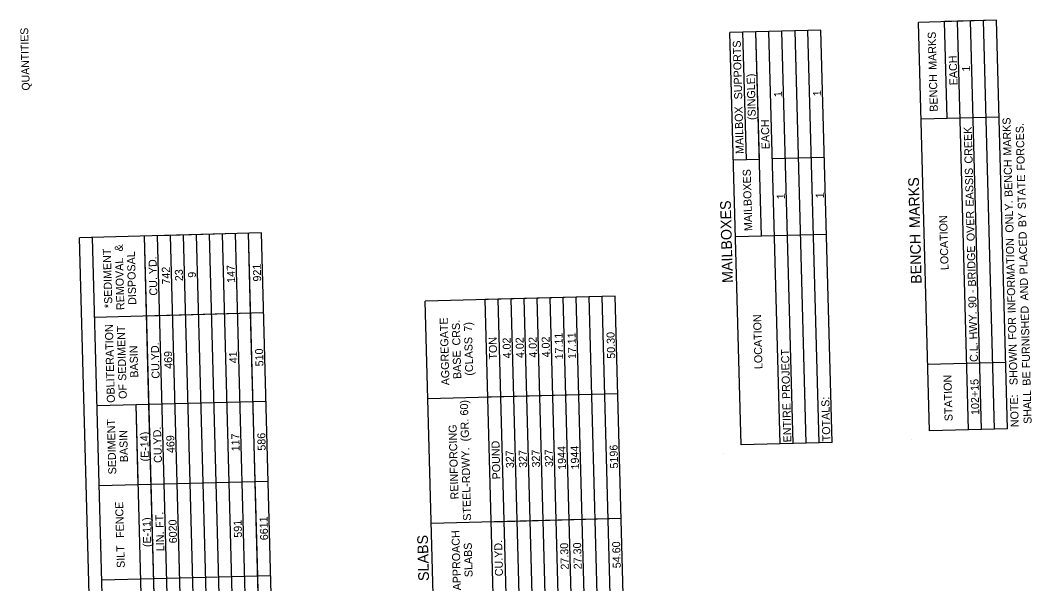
# Model space of a CAD drawing. Extents: x 1930091 to 1931962, y 596452 to 607874.
# Drawn here: x 1930287 to 1931046, y 600225 to 600647 of the extents above; entities that cross this region are included whole.
import ezdxf

# ---------------------------------------------------------------- set-up
doc = ezdxf.new("R2010")
doc.units = 0
for name, color, linetype in [('Default', 7, 'Continuous'), ('R_Border', 7, 'Continuous'), ('S_AREA_CALC', 7, 'Continuous')]:
    doc.layers.add(name, color=color, linetype=linetype)

msp = doc.modelspace()

# ---------------------------------------------------------------- linework, layer by layer
at = {"layer": 'Default'}
for p, q in [((1931019.12, 600647.31), (1930960.64, 600645.74)), ((1930968.85, 600339.7), (1930960.64, 600645.74)), ((1931019.12, 600647.31), (1930980.13, 600646.26)), ((1930982.08, 600573.65), (1930980.13, 600646.26)), ((1930998.09, 600340.48), (1930989.88, 600646.52)), ((1931007.84, 600340.74), (1930999.62, 600646.78)), ((1931017.58, 600341.01), (1931009.37, 600647.05)), ((1931027.33, 600341.27), (1931019.12, 600647.31)), ((1930887.59, 600639.9), (1930819.36, 600638.07)), ((1930829.11, 600638.33), (1930819.36, 600638.07)), ((1930827.66, 600329.1), (1930819.36, 600638.07)), ((1930831.68, 600542.81), (1930829.11, 600638.33)), ((1930887.59, 600639.9), (1930838.86, 600638.59)), ((1930842.97, 600485.57), (1930838.86, 600638.59)), ((1930841.42, 600543.08), (1930838.86, 600638.59)), ((1930856.9, 600329.89), (1930848.6, 600638.85)), ((1930866.64, 600330.15), (1930858.35, 600639.11)), ((1930876.39, 600330.41), (1930868.1, 600639.38)), ((1930886.14, 600330.67), (1930877.84, 600639.64)), ((1930895.88, 600330.94), (1930887.59, 600639.9)), ((1931021.06, 600574.7), (1930962.59, 600573.13)), ((1931021.06, 600574.7), (1930991.83, 600573.91)), ((1930841.42, 600543.08), (1930821.93, 600542.55)), ((1930890.15, 600544.38), (1930851.17, 600543.34)), ((1930890.15, 600544.38), (1930851.17, 600543.34)), ((1930468.12, 600487.92), (1930331.67, 600484.26)), ((1930458.38, 600487.66), (1930390.15, 600485.83)), ((1930443.87, 599211.51), (1930409.65, 600486.35)), ((1930453.61, 599211.78), (1930419.39, 600486.62)), ((1930463.36, 599212.04), (1930429.14, 600486.88)), ((1930473.11, 599212.3), (1930438.88, 600487.14)), ((1930482.85, 599212.56), (1930448.63, 600487.4)), ((1930492.6, 599212.82), (1930458.38, 600487.66)), ((1930459.99, 600427.72), (1930458.38, 600487.66)), ((1930502.35, 599213.08), (1930468.12, 600487.92)), ((1930891.7, 600486.88), (1930823.47, 600485.05)), ((1930891.7, 600486.88), (1930852.71, 600485.83)), ((1930365.9, 599209.42), (1930331.67, 600484.26)), ((1930366.93, 599534.24), (1930341.42, 600484.52)), ((1930405.92, 599535.29), (1930380.41, 600485.57)), ((1930383.79, 600359.35), (1930380.41, 600485.57)), ((1930424.37, 599210.99), (1930390.15, 600485.83)), ((1930434.12, 599211.25), (1930399.9, 600486.09)), ((1930733.24, 600440.58), (1930590.94, 600436.76)), ((1930605.18, 599906.55), (1930590.94, 600436.76)), ((1930733.24, 600440.58), (1930635.78, 600437.97)), ((1930643.13, 600164.09), (1930635.78, 600437.97)), ((1930659.76, 599908.02), (1930645.52, 600438.23)), ((1930669.5, 599908.28), (1930655.27, 600438.49)), ((1930679.25, 599908.54), (1930665.02, 600438.75)), ((1930689, 599908.8), (1930674.76, 600439.01)), ((1930698.74, 599909.07), (1930684.51, 600439.28)), ((1930708.49, 599909.33), (1930694.26, 600439.54)), ((1930718.24, 599909.59), (1930704, 600439.8)), ((1930727.98, 599909.85), (1930713.75, 600440.06)), ((1930737.73, 599910.11), (1930723.5, 600440.32)), ((1930747.47, 599910.37), (1930733.24, 600440.58)), ((1930469.73, 600427.98), (1930343.03, 600424.58)), ((1930469.73, 600427.98), (1930382.01, 600425.63)), ((1930465.27, 600230.84), (1930459.99, 600427.72)), ((1931026, 600390.97), (1930967.52, 600389.4)), ((1930735.2, 600367.49), (1930592.91, 600363.67)), ((1930735.2, 600367.49), (1930637.74, 600364.87)), ((1930471.51, 600361.71), (1930344.81, 600358.31)), ((1930380.82, 600106.66), (1930374.05, 600359.09)), ((1930375.66, 600299.15), (1930374.05, 600359.09)), ((1930471.51, 600361.71), (1930383.79, 600359.35)), ((1930392.56, 600032.85), (1930383.79, 600359.35)), ((1931027.33, 600341.27), (1930968.85, 600339.7)), ((1931027.33, 600341.27), (1930968.85, 600339.7)), ((1930895.88, 600330.94), (1930827.66, 600329.1)), ((1930895.88, 600330.94), (1930827.66, 600329.1)), ((1930473.12, 600301.77), (1930346.42, 600298.37)), ((1930473.12, 600301.77), (1930385.4, 600299.41)), ((1930737.72, 600273.92), (1930595.42, 600270.1)), ((1930737.72, 600273.92), (1930640.25, 600271.3)), ((1930475.02, 600231.1), (1930348.31, 600227.7)), ((1930465.27, 600230.84), (1930387.3, 600228.75)), ((1930474.57, 599884.36), (1930465.27, 600230.84))]:
    msp.add_line(p, q, dxfattribs=at)
at = {"layer": 'R_Border'}
for p, q in [((1930955.36, 600333.48), (1930955.36, 600333.48)), ((1930814.17, 600322.89), (1930814.17, 600322.89))]:
    msp.add_line(p, q, dxfattribs=at)

# ---------------------------------------------------------------- texts
at = {"layer": 'Default'}
for s, height, p in [(' MARKS', 6, (1930974.4, 600608.03)), (' SUPPORTS', 6, (1930828.64, 600585.83)), ('EACH', 6, (1930989.96, 600598.63)), ('1', 6, (1930999.44, 600608.89)), ('(SINGLE)', 6, (1930838.75, 600572.61)), ('BENCH', 6, (1930975.19, 600578.87)), ('1', 6, (1930858.47, 600589.77)), ('1', 6, (1930887.72, 600590.46)), ('MAILBOX', 6, (1930829.68, 600547.19)), ('EACH', 6, (1930849.09, 600550.74)), (' MARKS', 6, (1931030.45, 600543.71)), (' CREEK', 6, (1931001.35, 600537.75)), (' FORCES.', 6, (1931040.5, 600532.47)), (' BENCH', 6, (1931031.28, 600512.72)), ('MAILBOXES', 6, (1930836.11, 600489.44)), (' EASSIS', 6, (1931002.21, 600505.58)), (' MARKS', 8, (1930962.02, 600488.76)), (' STATE', 6, (1931041.28, 600503.58)), ('1', 6, (1930860.53, 600513.26)), ('1', 6, (1930889.77, 600513.95)), ('MAILBOXES', 8, (1930821.57, 600450.57)), (' ONLY.', 6, (1931032, 600485.98)), (' OVER', 6, (1931002.91, 600479.61)), (' BY', 6, (1931041.64, 600490.14)), ('LOCATION', 6, (1930983.25, 600460.19)), ('BENCH', 8, (1930963.07, 600449.89)), (' PLACED', 6, (1931042.59, 600454.72)), (' &', 6, (1930364.27, 600471.86)), (' INFORMATION', 6, (1931033.62, 600425.67)), ('*SEDIMENT', 6, (1930356.34, 600431.72)), ('DISPOSAL', 6, (1930374.28, 600434.1)), (' BRIDGE', 6, (1931003.82, 600445.6)), ('REMOVAL', 6, (1930365.39, 600430.21)), (' YD.', 6, (1930389.78, 600454.9)), ('921', 6, (1930467.9, 600451.61)), ('742', 6, (1930399.69, 600449.32)), ('23', 6, (1930409.37, 600451.88)), ('9', 6, (1930419.05, 600454.47)), ('147', 6, (1930448.42, 600450.6)), ('CU.', 6, (1930390.15, 600441.04)), (' AND', 6, (1931043.12, 600435.15)), (' -', 6, (1931003.95, 600440.74)), (' 90', 6, (1931004.25, 600429.5)), ('LOCATION', 6, (1930843.76, 600386)), (' HWY.', 6, (1931004.88, 600406.03)), (' FURNISHED', 6, (1931044.48, 600384.38)), ('OBLITERATION', 6, (1930358.25, 600360.72)), (' SEDIMENT', 6, (1930366.87, 600374.94)), ('AGGREGATE', 6, (1930609.06, 600373.85)), (' CRS.', 6, (1930617.33, 600401.45)), (' 7)', 6, (1930626.05, 600411.86)), (' FOR', 6, (1931034.15, 600405.77)), ('17.11', 6, (1930694.3, 600393.25)), ('17.11', 6, (1930704.04, 600393.51)), ('50.30', 6, (1930733.3, 600393.73)), ('BASIN', 6, (1930375.75, 600379.59)), ('CU.YD.', 6, (1930391.82, 600378.81)), ('(CLASS', 6, (1930626.88, 600381.08)), ('TON', 6, (1930644.86, 600393.12)), ('4.02', 6, (1930655.26, 600393.98)), ('4.02', 6, (1930665.01, 600394.24)), ('4.02', 6, (1930674.76, 600394.5)), ('4.02', 6, (1930684.5, 600394.76)), ('C.L.', 6, (1931005.28, 600391.39)), ('   SHOWN', 6, (1931035.18, 600367.35)), ('469', 6, (1930401.38, 600386.18)), ('41', 6, (1930450.03, 600390.4)), ('510', 6, (1930469.61, 600388.03)), ('BASE', 6, (1930617.94, 600378.57)), (' PROJECT', 6, (1930864.61, 600361.38)), ('STATION', 6, (1930986.29, 600346.97)), (' BE', 6, (1931044.83, 600371.31)), ('OF', 6, (1930367.17, 600363.69)), ('102+15', 6, (1931006.34, 600351.64)), ('NOTE:', 6, (1931035.85, 600342.47)), (' SHALL', 6, (1931045.6, 600342.73)), (' 60)', 6, (1930623.24, 600348.98)), ('ENTIRE', 6, (1930865.42, 600331.09)), ('TOTALS:', 6, (1930894.66, 600331.88)), ('SEDIMENT', 6, (1930359.31, 600307.12)), ('REINFORCING', 6, (1930615.86, 600288.36)), (' (GR.', 6, (1930623.76, 600329.55)), ('BASIN', 6, (1930368.07, 600316.23)), ('(E-14)', 6, (1930383.74, 600316.77)), ('CU.YD.', 6, (1930393.52, 600315.7)), ('469', 6, (1930403.07, 600323.07)), ('117', 6, (1930451.81, 600324.38)), ('586', 6, (1930471.3, 600324.87)), ('POUND', 6, (1930647.27, 600303.37)), ('1944', 6, (1930696.52, 600310.51)), ('1944', 6, (1930706.27, 600310.77)), ('5196', 6, (1930735.51, 600311.5)), ('STEEL-RDWY.', 6, (1930625.29, 600272.39)), ('327', 6, (1930657.47, 600311.78)), ('327', 6, (1930667.22, 600312.04)), ('327', 6, (1930676.96, 600312.3)), ('327', 6, (1930686.71, 600312.56)), ('  FENCE', 6, (1930365.21, 600255.01)), ('(E-11)', 6, (1930385.46, 600252.63)), (' FT.', 6, (1930394.89, 600264.78)), ('6611', 6, (1930473.1, 600257.77)), ('6020', 6, (1930404.89, 600255.46)), ('591', 6, (1930453.54, 600259.66)), ('LIN.', 6, (1930395.3, 600249.53)), (' SLABS', 8, (1930593.82, 600224.27)), ('APPROACH', 6, (1930617.69, 600220.2)), ('SILT', 6, (1930365.69, 600237.03)), ('SLABS', 6, (1930626.43, 600230.1)), ('CU.YD.', 6, (1930649.22, 600230.8)), ('27.30', 6, (1930698.53, 600235.76)), ('27.30', 6, (1930708.27, 600236.02)), ('54.60', 6, (1930737.51, 600236.81))]:
    msp.add_text(s, height=height, rotation=91.53769, dxfattribs=at).set_placement(p)
at = {"layer": 'S_AREA_CALC'}
msp.add_text('QUANTITIES', height=5.862, rotation=91.53769, dxfattribs=at).set_placement((1930294.42, 600594.75))

doc.saveas('drawing.dxf')
